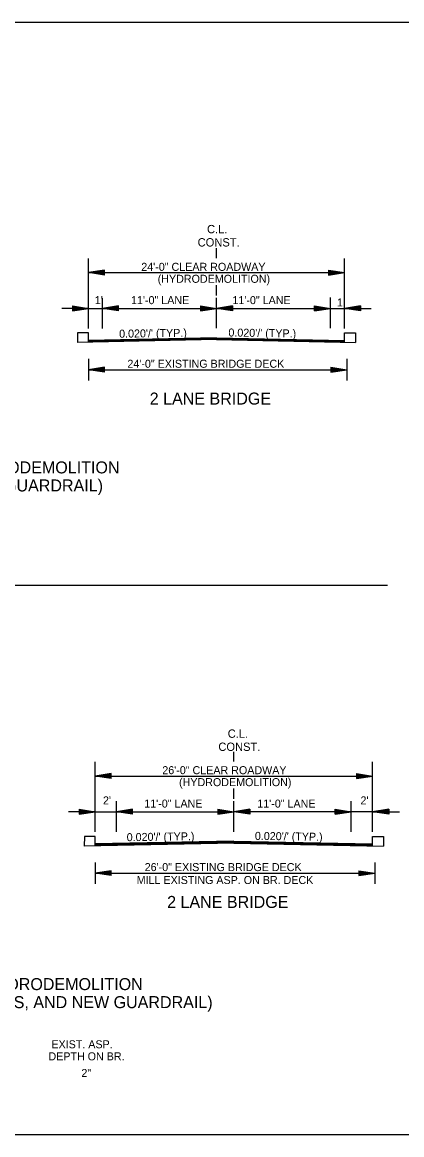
# Model space of a CAD drawing. Extents: x 544199 to 1930787, y -1968972 to 596640.
# Drawn here: x 544905 to 545260, y -1948346 to -1947303 of the extents above; entities that cross this region are included whole.
import ezdxf

# ---------------------------------------------------------------- set-up
doc = ezdxf.new("R2010")
doc.units = 0
for name, color, linetype in [('R_Border', 7, 'Continuous'), ('R_Draft', 7, 'Continuous'), ('R_No Plot', 7, 'Continuous')]:
    doc.layers.add(name, color=color, linetype=linetype)

msp = doc.modelspace()

# ---------------------------------------------------------------- linework, layer by layer
at = {"layer": 'R_Border'}
for p, q in [((544966.7, -1947594.5), (544956.5, -1947594.5)), ((544956.5, -1947594.5), (544956.5, -1947603.3)), ((544966.7, -1947603), (544966.7, -1947594.5)), ((545206.7, -1947603), (545206.7, -1947594.5)), ((545206.7, -1947594.5), (545216.9, -1947594.5)), ((545216.9, -1947594.5), (545216.9, -1947603.3)), ((544218.9, -1947830.7), (545246.9, -1947830.7)), ((544962.9, -1948066.4), (544962.8, -1948075.2)), ((544973, -1948066.4), (544962.9, -1948066.4)), ((544973, -1948074.8), (544973, -1948066.4)), ((545233, -1948074.8), (545233, -1948066.4)), ((545233, -1948066.4), (545243.2, -1948066.4)), ((545243.2, -1948066.4), (545243.2, -1948075.2))]:
    msp.add_line(p, q, dxfattribs=at)
at = {"layer": 'R_Draft'}
for p, q in [((545086.7, -1947524.5), (545086.7, -1947515.2)), ((544966.7, -1947590.3), (544966.7, -1947524.6)), ((545206.7, -1947590.3), (545206.7, -1947524.6)), ((544981.7, -1947535.7), (544966.7, -1947537.9)), ((544966.7, -1947537.9), (545206.7, -1947537.9)), ((544981.7, -1947540.2), (544966.7, -1947537.9)), ((544981.7, -1947536.1), (544969.2, -1947537.9)), ((544981.7, -1947539.8), (544969.2, -1947537.9)), ((544981.7, -1947536.4), (544971.8, -1947537.9)), ((544981.7, -1947539.4), (544971.8, -1947537.9)), ((544981.7, -1947536.8), (544974.3, -1947537.9)), ((544981.7, -1947539), (544974.3, -1947537.9)), ((544981.7, -1947537.2), (544976.8, -1947537.9)), ((544981.7, -1947538.7), (544976.8, -1947537.9)), ((544981.7, -1947537.6), (544979.3, -1947537.9)), ((544981.7, -1947538.3), (544979.3, -1947537.9)), ((544981.7, -1947540.2), (544981.7, -1947535.7)), ((545191.7, -1947535.7), (545206.7, -1947537.9)), ((545191.7, -1947535.7), (545191.7, -1947540.2)), ((545191.7, -1947536.1), (545204.2, -1947537.9)), ((545191.7, -1947536.4), (545201.6, -1947537.9)), ((545191.7, -1947536.8), (545199.1, -1947537.9)), ((545191.7, -1947537.2), (545196.6, -1947537.9)), ((545191.7, -1947537.6), (545194.1, -1947537.9)), ((545191.7, -1947540.2), (545206.7, -1947537.9)), ((545191.7, -1947538.7), (545196.6, -1947537.9)), ((545191.7, -1947539.4), (545201.6, -1947537.9)), ((545191.7, -1947539.8), (545204.2, -1947537.9)), ((545191.7, -1947539), (545199.1, -1947537.9)), ((545191.7, -1947538.3), (545194.1, -1947537.9)), ((545086.7, -1947559.5), (545086.7, -1947549.6)), ((544951.7, -1947569.2), (544966.7, -1947571.5)), ((544951.7, -1947569.2), (544951.7, -1947573.7)), ((544951.7, -1947569.6), (544964.2, -1947571.5)), ((544951.7, -1947570), (544961.6, -1947571.5)), ((544951.7, -1947570.4), (544959.1, -1947571.5)), ((544951.7, -1947570.7), (544956.6, -1947571.5)), ((544979.8, -1947590.3), (544979.8, -1947561.6)), ((544994.8, -1947569.2), (544979.8, -1947571.5)), ((544994.8, -1947569.6), (544982.3, -1947571.5)), ((544994.8, -1947570), (544984.9, -1947571.5)), ((544994.8, -1947570.4), (544987.4, -1947571.5)), ((544994.8, -1947570.7), (544990, -1947571.5)), ((544994.8, -1947573.7), (544994.8, -1947569.2)), ((545071.7, -1947569.2), (545086.7, -1947571.5)), ((545071.7, -1947569.2), (545071.7, -1947573.7)), ((545071.7, -1947569.6), (545084.2, -1947571.5)), ((545071.7, -1947570), (545081.6, -1947571.5)), ((545071.7, -1947570.4), (545079.1, -1947571.5)), ((545071.7, -1947570.7), (545076.6, -1947571.5)), ((545086.7, -1947590.1), (545086.7, -1947561.6)), ((545101.7, -1947569.2), (545086.7, -1947571.5)), ((545101.7, -1947569.6), (545089.2, -1947571.5)), ((545101.7, -1947570), (545091.8, -1947571.5)), ((545101.7, -1947570.4), (545094.3, -1947571.5)), ((545101.7, -1947570.7), (545096.8, -1947571.5)), ((545101.7, -1947569.2), (545101.7, -1947573.7)), ((545178.6, -1947569.2), (545193.6, -1947571.5)), ((545178.6, -1947573.7), (545178.6, -1947569.2)), ((545178.6, -1947569.6), (545191.1, -1947571.5)), ((545178.6, -1947570), (545188.5, -1947571.5)), ((545178.6, -1947570.4), (545186, -1947571.5)), ((545178.6, -1947570.7), (545183.4, -1947571.5)), ((545193.6, -1947589.9), (545193.6, -1947561.2)), ((545221.7, -1947569.2), (545206.7, -1947571.5)), ((545221.7, -1947569.6), (545209.2, -1947571.5)), ((545221.7, -1947570), (545211.8, -1947571.5)), ((545221.7, -1947570.4), (545214.3, -1947571.5)), ((545221.7, -1947570.7), (545216.8, -1947571.5)), ((545221.7, -1947569.2), (545221.7, -1947573.7)), ((544966.7, -1947571.5), (544941.7, -1947571.5)), ((544951.7, -1947571.1), (544954.1, -1947571.5)), ((544951.7, -1947573.7), (544966.7, -1947571.5)), ((544951.7, -1947572.2), (544956.6, -1947571.5)), ((544951.7, -1947573), (544961.6, -1947571.5)), ((544951.7, -1947573.3), (544964.2, -1947571.5)), ((544951.7, -1947572.6), (544959.1, -1947571.5)), ((544951.7, -1947571.8), (544954.1, -1947571.5)), ((544966.7, -1947571.5), (544979.8, -1947571.5)), ((544994.8, -1947573.7), (544979.8, -1947571.5)), ((544979.8, -1947571.5), (545086.7, -1947571.5)), ((544994.8, -1947573.3), (544982.3, -1947571.5)), ((544994.8, -1947573), (544984.9, -1947571.5)), ((544994.8, -1947572.6), (544987.4, -1947571.5)), ((544994.8, -1947572.2), (544990, -1947571.5)), ((544994.8, -1947571.1), (544992.5, -1947571.5)), ((544994.8, -1947571.8), (544992.5, -1947571.5)), ((545071.7, -1947571.1), (545074.1, -1947571.5)), ((545071.7, -1947573.7), (545086.7, -1947571.5)), ((545071.7, -1947572.2), (545076.6, -1947571.5)), ((545071.7, -1947573), (545081.6, -1947571.5)), ((545071.7, -1947573.3), (545084.2, -1947571.5)), ((545071.7, -1947572.6), (545079.1, -1947571.5)), ((545071.7, -1947571.8), (545074.1, -1947571.5)), ((545101.7, -1947573.7), (545086.7, -1947571.5)), ((545086.7, -1947571.5), (545193.6, -1947571.5)), ((545101.7, -1947573.3), (545089.2, -1947571.5)), ((545101.7, -1947573), (545091.8, -1947571.5)), ((545101.7, -1947572.6), (545094.3, -1947571.5)), ((545101.7, -1947572.2), (545096.8, -1947571.5)), ((545101.7, -1947571.1), (545099.3, -1947571.5)), ((545101.7, -1947571.8), (545099.3, -1947571.5)), ((545178.6, -1947571.1), (545180.9, -1947571.5)), ((545178.6, -1947573.7), (545193.6, -1947571.5)), ((545178.6, -1947572.2), (545183.4, -1947571.5)), ((545178.6, -1947573), (545188.5, -1947571.5)), ((545178.6, -1947573.3), (545191.1, -1947571.5)), ((545178.6, -1947572.6), (545186, -1947571.5)), ((545178.6, -1947571.8), (545180.9, -1947571.5)), ((545193.6, -1947571.5), (545206.7, -1947571.5)), ((545221.7, -1947573.7), (545206.7, -1947571.5)), ((545206.7, -1947571.5), (545231.7, -1947571.5)), ((545221.7, -1947573.3), (545209.2, -1947571.5)), ((545221.7, -1947573), (545211.8, -1947571.5)), ((545221.7, -1947572.6), (545214.3, -1947571.5)), ((545221.7, -1947572.2), (545216.8, -1947571.5)), ((545221.7, -1947571.1), (545219.3, -1947571.5)), ((545221.7, -1947571.8), (545219.3, -1947571.5)), ((545086.7, -1947600.7), (544956.5, -1947603.3)), ((545086.7, -1947599.1), (544966.7, -1947601.5)), ((545086.7, -1947599.4), (544966.7, -1947601.8)), ((545086.7, -1947599.7), (544966.7, -1947602.1)), ((545086.7, -1947600), (544966.7, -1947602.4)), ((545086.7, -1947600.3), (544966.7, -1947602.7)), ((545086.7, -1947600.6), (544966.7, -1947603)), ((545086.7, -1947599.1), (545206.7, -1947601.5)), ((545086.7, -1947599.4), (545206.7, -1947601.8)), ((545086.7, -1947599.7), (545206.7, -1947602.1)), ((545086.7, -1947600), (545206.7, -1947602.4)), ((545086.7, -1947600.3), (545206.7, -1947602.7)), ((545086.7, -1947600.6), (545206.7, -1947603)), ((545086.7, -1947600.7), (545216.9, -1947603.3)), ((544966.7, -1947618.9), (544966.7, -1947638.9)), ((545208.7, -1947618.9), (545208.7, -1947638.9)), ((544981.7, -1947626.7), (544966.7, -1947628.9)), ((544966.7, -1947628.9), (545206.7, -1947628.9)), ((544981.7, -1947631.2), (544966.7, -1947628.9)), ((544981.7, -1947627.1), (544969.2, -1947628.9)), ((544981.7, -1947630.8), (544969.2, -1947628.9)), ((544981.7, -1947627.4), (544971.8, -1947628.9)), ((544981.7, -1947630.4), (544971.8, -1947628.9)), ((544981.7, -1947627.8), (544974.3, -1947628.9)), ((544981.7, -1947630.1), (544974.3, -1947628.9)), ((544981.7, -1947628.2), (544976.8, -1947628.9)), ((544981.7, -1947629.7), (544976.8, -1947628.9)), ((544981.7, -1947628.6), (544979.3, -1947628.9)), ((544981.7, -1947629.3), (544979.3, -1947628.9)), ((544981.7, -1947631.2), (544981.7, -1947626.7)), ((545193.7, -1947626.7), (545208.7, -1947628.9)), ((545193.7, -1947626.7), (545193.7, -1947631.2)), ((545193.7, -1947627.1), (545206.2, -1947628.9)), ((545193.7, -1947627.4), (545203.6, -1947628.9)), ((545193.7, -1947627.8), (545201.1, -1947628.9)), ((545193.7, -1947628.2), (545198.6, -1947628.9)), ((545193.7, -1947628.6), (545196.1, -1947628.9)), ((545193.7, -1947631.2), (545208.7, -1947628.9)), ((545193.7, -1947629.7), (545198.6, -1947628.9)), ((545193.7, -1947630.4), (545203.6, -1947628.9)), ((545193.7, -1947630.8), (545206.2, -1947628.9)), ((545193.7, -1947630.1), (545201.1, -1947628.9)), ((545193.7, -1947629.3), (545196.1, -1947628.9)), ((545103, -1947996.1), (545103, -1947986.8)), ((544973, -1948061.9), (544973, -1947996.2)), ((545233, -1948061.9), (545233, -1947996.2)), ((544988, -1948007.3), (544973, -1948009.6)), ((544988, -1948007.7), (544975.5, -1948009.6)), ((544988, -1948008.1), (544978.1, -1948009.6)), ((544988, -1948008.4), (544980.6, -1948009.6)), ((544988, -1948011.8), (544988, -1948007.3)), ((545218, -1948007.3), (545233, -1948009.6)), ((545218, -1948007.3), (545218, -1948011.8)), ((545218, -1948007.7), (545230.5, -1948009.6)), ((545218, -1948008.1), (545227.9, -1948009.6)), ((545218, -1948008.4), (545225.4, -1948009.6)), ((544973, -1948009.6), (545233, -1948009.6)), ((544988, -1948011.8), (544973, -1948009.6)), ((544988, -1948011.4), (544975.5, -1948009.6)), ((544988, -1948011.1), (544978.1, -1948009.6)), ((544988, -1948010.7), (544980.6, -1948009.6)), ((544988, -1948008.8), (544983.1, -1948009.6)), ((544988, -1948010.3), (544983.1, -1948009.6)), ((544988, -1948009.2), (544985.7, -1948009.6)), ((544988, -1948009.9), (544985.7, -1948009.6)), ((545218, -1948008.8), (545222.9, -1948009.6)), ((545218, -1948009.2), (545220.4, -1948009.6)), ((545218, -1948011.8), (545233, -1948009.6)), ((545218, -1948010.3), (545222.9, -1948009.6)), ((545218, -1948011.1), (545227.9, -1948009.6)), ((545218, -1948011.4), (545230.5, -1948009.6)), ((545218, -1948010.7), (545225.4, -1948009.6)), ((545218, -1948009.9), (545220.4, -1948009.6)), ((545103, -1948031.1), (545103, -1948021.2)), ((544993, -1948061.9), (544993, -1948033.2)), ((545103, -1948061.8), (545103, -1948033.2)), ((545213, -1948061.9), (545213, -1948033.2)), ((544973, -1948043.1), (544948, -1948043.1)), ((544958, -1948040.8), (544973, -1948043.1)), ((544958, -1948040.8), (544958, -1948045.3)), ((544958, -1948041.2), (544970.5, -1948043.1)), ((544958, -1948041.6), (544967.9, -1948043.1)), ((544958, -1948042), (544965.4, -1948043.1)), ((544958, -1948042.4), (544962.9, -1948043.1)), ((544958, -1948042.7), (544960.4, -1948043.1)), ((544958, -1948045.3), (544973, -1948043.1)), ((544958, -1948043.8), (544962.9, -1948043.1)), ((544958, -1948044.6), (544967.9, -1948043.1)), ((544958, -1948045), (544970.5, -1948043.1)), ((544958, -1948044.2), (544965.4, -1948043.1)), ((544958, -1948043.5), (544960.4, -1948043.1)), ((544973, -1948043.1), (545103, -1948043.1)), ((545008, -1948040.8), (544993, -1948043.1)), ((545008, -1948045.3), (544993, -1948043.1)), ((545008, -1948041.2), (544995.5, -1948043.1)), ((545008, -1948045), (544995.5, -1948043.1)), ((545008, -1948041.6), (544998.1, -1948043.1)), ((545008, -1948044.6), (544998.1, -1948043.1)), ((545008, -1948042), (545000.6, -1948043.1)), ((545008, -1948044.2), (545000.6, -1948043.1)), ((545008, -1948042.4), (545003.1, -1948043.1)), ((545008, -1948043.8), (545003.1, -1948043.1)), ((545008, -1948042.7), (545005.7, -1948043.1)), ((545008, -1948043.5), (545005.7, -1948043.1)), ((545008, -1948045.3), (545008, -1948040.8)), ((545088, -1948040.8), (545103, -1948043.1)), ((545088, -1948040.8), (545088, -1948045.3)), ((545088, -1948041.2), (545100.5, -1948043.1)), ((545088, -1948041.6), (545097.9, -1948043.1)), ((545088, -1948042), (545095.4, -1948043.1)), ((545088, -1948042.4), (545092.9, -1948043.1)), ((545088, -1948042.7), (545090.4, -1948043.1)), ((545088, -1948045.3), (545103, -1948043.1)), ((545088, -1948043.8), (545092.9, -1948043.1)), ((545088, -1948044.6), (545097.9, -1948043.1)), ((545088, -1948045), (545100.5, -1948043.1)), ((545088, -1948044.2), (545095.4, -1948043.1)), ((545088, -1948043.5), (545090.4, -1948043.1)), ((545118, -1948040.8), (545103, -1948043.1)), ((545233, -1948043.1), (545103, -1948043.1)), ((545118, -1948045.3), (545103, -1948043.1)), ((545118, -1948041.2), (545105.5, -1948043.1)), ((545118, -1948045), (545105.5, -1948043.1)), ((545118, -1948041.6), (545108.1, -1948043.1)), ((545118, -1948044.6), (545108.1, -1948043.1)), ((545118, -1948042), (545110.6, -1948043.1)), ((545118, -1948044.2), (545110.6, -1948043.1)), ((545118, -1948042.4), (545113.1, -1948043.1)), ((545118, -1948043.8), (545113.1, -1948043.1)), ((545118, -1948042.7), (545115.7, -1948043.1)), ((545118, -1948043.5), (545115.7, -1948043.1)), ((545118, -1948040.8), (545118, -1948045.3)), ((545198, -1948040.8), (545213, -1948043.1)), ((545198, -1948045.3), (545198, -1948040.8)), ((545198, -1948041.2), (545210.5, -1948043.1)), ((545198, -1948041.6), (545207.9, -1948043.1)), ((545198, -1948042), (545205.4, -1948043.1)), ((545198, -1948042.4), (545202.9, -1948043.1)), ((545198, -1948042.7), (545200.4, -1948043.1)), ((545198, -1948045.3), (545213, -1948043.1)), ((545198, -1948043.8), (545202.9, -1948043.1)), ((545198, -1948044.6), (545207.9, -1948043.1)), ((545198, -1948045), (545210.5, -1948043.1)), ((545198, -1948044.2), (545205.4, -1948043.1)), ((545198, -1948043.5), (545200.4, -1948043.1)), ((545248, -1948040.8), (545233, -1948043.1)), ((545248, -1948045.3), (545233, -1948043.1)), ((545233, -1948043.1), (545258, -1948043.1)), ((545248, -1948041.2), (545235.5, -1948043.1)), ((545248, -1948045), (545235.5, -1948043.1)), ((545248, -1948041.6), (545238.1, -1948043.1)), ((545248, -1948044.6), (545238.1, -1948043.1)), ((545248, -1948042), (545240.6, -1948043.1)), ((545248, -1948044.2), (545240.6, -1948043.1)), ((545248, -1948042.4), (545243.1, -1948043.1)), ((545248, -1948043.8), (545243.1, -1948043.1)), ((545248, -1948042.7), (545245.7, -1948043.1)), ((545248, -1948043.5), (545245.7, -1948043.1)), ((545248, -1948040.8), (545248, -1948045.3)), ((545103, -1948070.7), (544973, -1948073.3)), ((545103, -1948071), (544973, -1948073.6)), ((545103, -1948071.3), (544973, -1948073.9)), ((545103, -1948070.7), (545233, -1948073.3)), ((545103, -1948071), (545233, -1948073.6)), ((545103, -1948071.3), (545233, -1948073.9)), ((545103.1, -1948072.4), (544962.8, -1948075.2)), ((545103, -1948071.6), (544973, -1948074.2)), ((545103, -1948071.9), (544973, -1948074.5)), ((545103.1, -1948072.2), (544973, -1948074.8)), ((545103, -1948071.6), (545233, -1948074.2)), ((545103, -1948071.9), (545233, -1948074.5)), ((545103, -1948072.2), (545233, -1948074.8)), ((545103, -1948072.4), (545243.2, -1948075.2)), ((544973, -1948090.6), (544973, -1948110.6)), ((545235, -1948090.6), (545235, -1948110.6)), ((544988, -1948098.3), (544973, -1948100.6)), ((544973, -1948100.6), (545233, -1948100.6)), ((544988, -1948102.8), (544973, -1948100.6)), ((544988, -1948098.7), (544975.5, -1948100.6)), ((544988, -1948102.4), (544975.5, -1948100.6)), ((544988, -1948099.1), (544978.1, -1948100.6)), ((544988, -1948102.1), (544978.1, -1948100.6)), ((544988, -1948099.4), (544980.6, -1948100.6)), ((544988, -1948101.7), (544980.6, -1948100.6)), ((544988, -1948099.8), (544983.1, -1948100.6)), ((544988, -1948101.3), (544983.1, -1948100.6)), ((544988, -1948100.2), (544985.7, -1948100.6)), ((544988, -1948100.9), (544985.7, -1948100.6)), ((544988, -1948102.8), (544988, -1948098.3)), ((545220, -1948098.3), (545235, -1948100.6)), ((545220, -1948098.3), (545220, -1948102.8)), ((545220, -1948098.7), (545232.5, -1948100.6)), ((545220, -1948099.1), (545229.9, -1948100.6)), ((545220, -1948099.4), (545227.4, -1948100.6)), ((545220, -1948099.8), (545224.9, -1948100.6)), ((545220, -1948100.2), (545222.4, -1948100.6)), ((545220, -1948102.8), (545235, -1948100.6)), ((545220, -1948101.3), (545224.9, -1948100.6)), ((545220, -1948102.1), (545229.9, -1948100.6)), ((545220, -1948102.4), (545232.5, -1948100.6)), ((545220, -1948101.7), (545227.4, -1948100.6)), ((545220, -1948100.9), (545222.4, -1948100.6))]:
    msp.add_line(p, q, dxfattribs=at)
at = {"layer": 'R_No Plot'}
for points in [[(544198.9, -1947831), (544198.9, -1947303.4), (545383, -1947303.4), (545383, -1947352.8), (545560.6, -1947352.8), (545560.6, -1947370.6), (545578.8, -1947370.6), (545578.8, -1947367.4), (545656.5, -1947367.4)], [(545794.3, -1947831), (545794.3, -1948345.7), (544198.9, -1948345.7), (544198.9, -1947831)]]:
    msp.add_lwpolyline(points, dxfattribs=at)

# ---------------------------------------------------------------- texts
at = {"layer": 'R_Draft'}
for s, height, p in [('C.L.', 7.8, (545077.8, -1947501.1)), ('CONST.', 7.8, (545069, -1947513.5)), ('24\'-0" CLEAR ROADWAY ', 7.5, (545016.2, -1947536.3)), ('(HYDRODEMOLITION)', 7.5, (545031.6, -1947547.5)), ("1'", 7.5, (544972.6, -1947567.5)), ('11\'-0" LANE', 7.5, (545006.6, -1947567.5)), ('11\'-0" LANE', 7.5, (545101.6, -1947567.5)), ("1'", 7.5, (545199.6, -1947569.7)), ('24\'-0" EXISTING BRIDGE DECK', 7.5, (545003.2, -1947627.1)), ('2 LANE BRIDGE', 11.25, (545024.1, -1947661.6)), ('24 FT. CLEAR ROADWAY BRIDGE - HYDRODEMOLITION', 11.25, (544592.9, -1947726.1)), ('(ROADWAY TRANSITIONS AND NEW GUARDRAIL)', 11.25, (544620.1, -1947743)), ('C.L.', 7.8, (545097.2, -1947973.8)), ('CONST.', 7.8, (545088.4, -1947986.1)), ('26\'-0" CLEAR ROADWAY ', 7.5, (545035.9, -1948007.9)), ('(HYDRODEMOLITION)', 7.5, (545051.6, -1948019.1)), ("2'", 7.5, (544980.3, -1948036.2)), ("2'", 7.5, (545221.6, -1948036.2)), ('11\'-0" LANE', 7.5, (545019, -1948039.2)), ('11\'-0" LANE', 7.5, (545124.9, -1948039.2)), ('26\'-0" EXISTING BRIDGE DECK', 7.5, (545019.4, -1948098.7)), ('MILL EXISTING ASP. ON BR. DECK', 7.5, (545011.9, -1948110.8)), ('2 LANE BRIDGE', 11.25, (545040.4, -1948133.2)), ('26 FT. CLEAR ROADWAY BRIDGE - HYDRODEMOLITION', 11.25, (544614.7, -1948210.2)), ('(MILLING ON BR. DECK, ROADWAY TRANSITIONS, AND NEW GUARDRAIL)', 11.25, (544548.1, -1948227.1)), (' EXIST. ASP. ', 7.5, (544929.2, -1948264.7)), ('DEPTH ON BR. ', 7.5, (544929.2, -1948276)), ('2"', 7.5, (544960.1, -1948291.6))]:
    msp.add_text(s, height=height, dxfattribs=at).set_placement(p)
for rotation, p in [(0.8719, (544995.5, -1947599)), (359.1281, (545097.8, -1947597.8)), (0.8719, (545002.6, -1948070.7)), (359.1281, (545122.6, -1948069.4))]:
    msp.add_text("0.020'/' (TYP.)", height=7.5, rotation=rotation, dxfattribs=at).set_placement(p)

doc.saveas('drawing.dxf')
